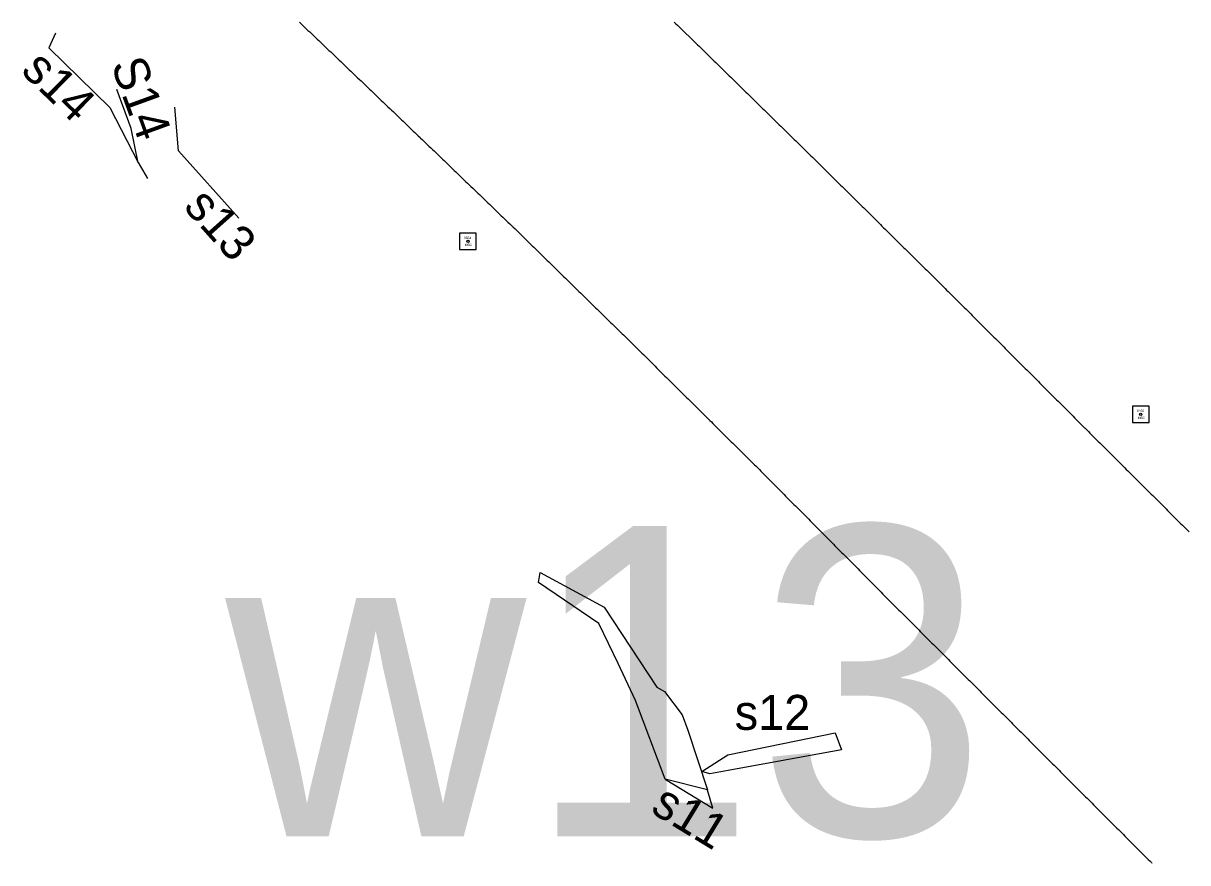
# Model space of a CAD drawing. Extents: x 205929 to 2357175, y -1785700 to 846739.
# Drawn here: x 2019173.3 to 2019672.3, y 816619 to 816978.9 of the extents above; entities that cross this region are included whole.
import ezdxf

# ---------------------------------------------------------------- set-up
doc = ezdxf.new("R2010")
doc.units = 0
for name, color, linetype in [('Default', 7, 'Continuous'), ('RD_EV_JTrib', 7, 'Continuous'), ('RD_EV_JW', 7, 'Continuous'), ('RD_EV_TX', 7, 'Continuous'), ('RD_HC_Survey', 7, 'Continuous'), ('RD_HC_txCode', 7, 'Continuous'), ('RD_Sketch1', 7, 'Continuous'), ('RD_SMD_Locator', 7, 'Continuous')]:
    doc.layers.add(name, color=color, linetype=linetype)

# ---------------------------------------------------------------- blocks, each defined once
blk = doc.blocks.new('POL00034')
at = {"layer": 'Default'}
blk.add_lwpolyline([(2.23, 0.45), (4.16, -2.1), (4.78, -3.77), (6.93, -10.27), (2.31, -9.09), (-0.91, -0.52), (-2.8, 3.49), (-4.89, 7.87), (-11.45, 12.32), (-11.27, 13.43), (-4.32, 9.65), (1.43, 0.94)], close=True, dxfattribs=at)
blk = doc.blocks.new('POL00048')
at = {"layer": 'Default'}
blk.add_lwpolyline([(-5.27, -0.11), (6.41, 2.28), (7.1, 0.43), (-5.25, -1.82), (-7.25, -2.18), (-8.1, -1.93)], close=True, dxfattribs=at)
blk = doc.blocks.new('ARC0002H')
at = {"layer": 'Default'}
blk.add_lwpolyline([(-3.48, 2.12), (1.72, -1.04), (1.14, 0.94)], dxfattribs=at)
blk = doc.blocks.new('ARC0002I')
at = {"layer": 'Default'}
blk.add_lwpolyline([(-5.07, 7.29), (-5.83, 5.69), (0.84, -0.82), (3.92, -6.81), (4.91, -8.56)], dxfattribs=at)
blk = doc.blocks.new('ARC0002J')
at = {"layer": 'Default'}
blk.add_lwpolyline([(4.87, -5.45), (-1.7, 1.9), (-2.09, 6.64)], dxfattribs=at)
blk = doc.blocks.new('ARC00038')
at = {"layer": 'Default'}
blk.add_lwpolyline([(0.9, -4.08), (0.13, -0.35), (-1.41, 3.89), (-1.41, 3.85)], dxfattribs=at)

msp = doc.modelspace()

# ---------------------------------------------------------------- linework, layer by layer
at = {"layer": 'RD_HC_Survey'}
for points in [[(2019367.37, 816888.95), (2019360.3, 816888.95), (2019360.3, 816881.88), (2019367.37, 816881.88)], [(2019655.76, 816814.79), (2019648.69, 816814.79), (2019648.69, 816807.72), (2019655.76, 816807.72)]]:
    msp.add_lwpolyline(points, close=True, dxfattribs=at)
for centre in [(2019363.84, 816885.42), (2019652.22, 816811.25)]:
    msp.add_circle(centre, 0.5, dxfattribs=at)
at = {"layer": 'RD_Sketch1'}
for points in [[(2019291.71, 816979.34), (2019292.44, 816978.65), (2019293.16, 816977.96), (2019293.89, 816977.28), (2019294.62, 816976.59), (2019295.34, 816975.9), (2019296.07, 816975.21), (2019296.07, 816975.21), (2019296.8, 816974.53), (2019297.52, 816973.84), (2019298.25, 816973.15), (2019298.98, 816972.47), (2019299.29, 816972.17), (2019300.01, 816971.48), (2019300.73, 816970.79), (2019301.45, 816970.09), (2019302.18, 816969.4), (2019302.9, 816968.71), (2019303.62, 816968.02), (2019304.34, 816967.33), (2019305.07, 816966.64), (2019305.79, 816965.94), (2019306.51, 816965.25), (2019307.23, 816964.56), (2019307.95, 816963.87), (2019308.68, 816963.18), (2019309.4, 816962.49), (2019310.12, 816961.79), (2019310.84, 816961.1), (2019311.57, 816960.41), (2019312.29, 816959.72), (2019313.01, 816959.03), (2019313.73, 816958.34), (2019314.45, 816957.64), (2019315.18, 816956.95), (2019315.9, 816956.26), (2019316.62, 816955.57), (2019317.34, 816954.88), (2019318.06, 816954.19), (2019318.79, 816953.49), (2019319.51, 816952.8), (2019320.23, 816952.11), (2019320.95, 816951.42), (2019321.68, 816950.73), (2019322.4, 816950.04), (2019323.12, 816949.34), (2019323.84, 816948.65), (2019324.56, 816947.96), (2019325.29, 816947.27), (2019326.01, 816946.58), (2019326.73, 816945.89), (2019327.45, 816945.19), (2019328.17, 816944.5), (2019328.9, 816943.81), (2019329.62, 816943.12), (2019330.34, 816942.43), (2019331.06, 816941.74), (2019331.79, 816941.04), (2019332.51, 816940.35), (2019333.23, 816939.66), (2019333.95, 816938.97), (2019334.67, 816938.28), (2019335.4, 816937.59), (2019336.12, 816936.89), (2019336.84, 816936.2), (2019337.56, 816935.51), (2019338.29, 816934.82), (2019339.01, 816934.13), (2019339.73, 816933.44), (2019340.45, 816932.74), (2019341.17, 816932.05), (2019341.9, 816931.36), (2019341.9, 816931.36), (2019342.62, 816930.67), (2019343.34, 816929.98), (2019343.59, 816929.74), (2019344.31, 816929.05), (2019345.03, 816928.35), (2019345.75, 816927.66), (2019346.47, 816926.96), (2019347.19, 816926.27), (2019347.91, 816925.58), (2019348.63, 816924.88), (2019349.35, 816924.19), (2019350.07, 816923.5), (2019350.79, 816922.8), (2019351.51, 816922.11), (2019352.23, 816921.41), (2019352.95, 816920.72), (2019353.67, 816920.03), (2019354.39, 816919.33), (2019355.11, 816918.64), (2019355.83, 816917.95), (2019356.55, 816917.25), (2019357.27, 816916.56), (2019357.99, 816915.86), (2019358.71, 816915.17), (2019359.43, 816914.48), (2019360.15, 816913.78), (2019360.87, 816913.09), (2019361.59, 816912.4), (2019362.31, 816911.7), (2019363.03, 816911.01), (2019363.75, 816910.31), (2019364.47, 816909.62), (2019365.19, 816908.93), (2019365.91, 816908.23), (2019366.63, 816907.54), (2019367.35, 816906.85), (2019368.07, 816906.15), (2019368.79, 816905.46), (2019369.52, 816904.76), (2019370.24, 816904.07), (2019370.96, 816903.38), (2019371.68, 816902.68), (2019372.4, 816901.99), (2019373.12, 816901.3), (2019373.84, 816900.6), (2019374.56, 816899.91), (2019375.28, 816899.21), (2019376, 816898.52), (2019376.72, 816897.83), (2019377.44, 816897.13), (2019378.16, 816896.44), (2019378.88, 816895.75), (2019379.6, 816895.05), (2019380.32, 816894.36), (2019381.04, 816893.66), (2019381.76, 816892.97), (2019382.48, 816892.28), (2019383.2, 816891.58), (2019383.92, 816890.89), (2019384.64, 816890.2), (2019385.36, 816889.5), (2019386.08, 816888.81), (2019386.43, 816888.47), (2019387.15, 816887.77), (2019387.15, 816887.77), (2019387.86, 816887.07), (2019388.58, 816886.37), (2019389.29, 816885.67), (2019390.01, 816884.97), (2019390.72, 816884.27), (2019391.44, 816883.57), (2019392.15, 816882.87), (2019392.86, 816882.17), (2019393.58, 816881.47), (2019394.29, 816880.77), (2019395.01, 816880.07), (2019395.72, 816879.37), (2019396.44, 816878.68), (2019397.15, 816877.98), (2019397.87, 816877.28), (2019398.58, 816876.58), (2019399.3, 816875.88), (2019400.01, 816875.18), (2019400.73, 816874.48), (2019401.44, 816873.78), (2019402.16, 816873.08), (2019402.87, 816872.38), (2019403.58, 816871.68), (2019404.3, 816870.98), (2019405.01, 816870.28), (2019405.73, 816869.58), (2019406.44, 816868.88), (2019407.16, 816868.18), (2019407.87, 816867.48), (2019408.59, 816866.78), (2019409.3, 816866.08), (2019410.02, 816865.39), (2019410.73, 816864.69), (2019411.45, 816863.99), (2019412.16, 816863.29), (2019412.87, 816862.59), (2019413.59, 816861.89), (2019414.3, 816861.19), (2019415.02, 816860.49), (2019415.73, 816859.79), (2019416.45, 816859.09), (2019417.16, 816858.39), (2019417.88, 816857.69), (2019418.59, 816856.99), (2019419.31, 816856.29), (2019420.02, 816855.59), (2019420.74, 816854.89), (2019421.45, 816854.19), (2019422.17, 816853.49), (2019422.88, 816852.79), (2019423.59, 816852.1), (2019424.31, 816851.4), (2019425.02, 816850.7), (2019425.74, 816850), (2019426.45, 816849.3), (2019427.17, 816848.6), (2019427.88, 816847.9), (2019428.6, 816847.2), (2019429.31, 816846.5), (2019430.03, 816845.8), (2019430.55, 816845.29), (2019431.26, 816844.59), (2019431.97, 816843.88), (2019432.68, 816843.18), (2019432.68, 816843.18), (2019433.39, 816842.47), (2019434.1, 816841.77), (2019434.81, 816841.07), (2019435.52, 816840.36), (2019436.23, 816839.66), (2019436.94, 816838.95), (2019437.65, 816838.25), (2019438.36, 816837.55), (2019439.07, 816836.84), (2019439.78, 816836.14), (2019440.49, 816835.43), (2019441.2, 816834.73), (2019441.91, 816834.03), (2019442.62, 816833.32), (2019443.33, 816832.62), (2019444.04, 816831.91), (2019444.75, 816831.21), (2019445.46, 816830.51), (2019446.17, 816829.8), (2019446.88, 816829.1), (2019447.59, 816828.39), (2019448.3, 816827.69), (2019449.01, 816826.98), (2019449.72, 816826.28), (2019450.43, 816825.58), (2019451.14, 816824.87), (2019451.85, 816824.17), (2019452.56, 816823.46), (2019453.27, 816822.76), (2019453.98, 816822.06), (2019454.69, 816821.35), (2019455.4, 816820.65), (2019456.11, 816819.94), (2019456.82, 816819.24), (2019457.53, 816818.54), (2019458.24, 816817.83), (2019458.95, 816817.13), (2019459.66, 816816.42), (2019460.37, 816815.72), (2019461.08, 816815.02), (2019461.79, 816814.31), (2019462.5, 816813.61), (2019463.21, 816812.9), (2019463.92, 816812.2), (2019464.63, 816811.5), (2019465.34, 816810.79), (2019466.05, 816810.09), (2019466.76, 816809.38), (2019467.47, 816808.68), (2019468.18, 816807.97), (2019468.89, 816807.27), (2019469.6, 816806.57), (2019470.31, 816805.86), (2019471.02, 816805.16), (2019471.73, 816804.45), (2019472.44, 816803.75), (2019473.15, 816803.05), (2019473.86, 816802.34), (2019474.57, 816801.64), (2019475.28, 816800.93), (2019475.99, 816800.23), (2019476.7, 816799.53), (2019477.41, 816798.82), (2019478.12, 816798.12), (2019478.12, 816798.12), (2019478.83, 816797.41), (2019479.54, 816796.71), (2019480.25, 816796.01), (2019480.96, 816795.3), (2019481.67, 816794.6), (2019482.38, 816793.89), (2019483.09, 816793.19), (2019483.8, 816792.48), (2019484.51, 816791.78), (2019485.22, 816791.08), (2019485.93, 816790.37), (2019486.64, 816789.67), (2019487.35, 816788.96), (2019488.05, 816788.27), (2019488.76, 816787.56), (2019489.46, 816786.85), (2019490.17, 816786.14), (2019490.87, 816785.43), (2019491.58, 816784.72), (2019492.28, 816784.01), (2019492.98, 816783.3), (2019493.69, 816782.6), (2019494.39, 816781.89), (2019495.1, 816781.18), (2019495.8, 816780.47), (2019496.51, 816779.76), (2019497.21, 816779.05), (2019497.92, 816778.34), (2019498.62, 816777.63), (2019499.32, 816776.92), (2019500.03, 816776.21), (2019500.73, 816775.5), (2019501.44, 816774.79), (2019502.14, 816774.08), (2019502.85, 816773.37), (2019503.55, 816772.66), (2019504.26, 816771.95), (2019504.96, 816771.24), (2019505.66, 816770.53), (2019506.37, 816769.82), (2019507.07, 816769.11), (2019507.78, 816768.4), (2019508.48, 816767.69), (2019509.19, 816766.98), (2019509.89, 816766.27), (2019510.6, 816765.56), (2019511.3, 816764.85), (2019512.01, 816764.14), (2019512.71, 816763.43), (2019513.41, 816762.72), (2019514.12, 816762.01), (2019514.82, 816761.3), (2019515.53, 816760.59), (2019516.23, 816759.88), (2019516.94, 816759.18), (2019517.64, 816758.47), (2019518.35, 816757.76), (2019519.05, 816757.05), (2019519.75, 816756.34), (2019520.46, 816755.63), (2019521.16, 816754.92), (2019521.87, 816754.21), (2019522.57, 816753.5), (2019523.28, 816752.79), (2019523.28, 816752.79), (2019523.98, 816752.08), (2019524.69, 816751.37), (2019525.39, 816750.66), (2019526.09, 816749.95), (2019526.8, 816749.24), (2019527.5, 816748.53), (2019528.21, 816747.82), (2019528.91, 816747.11), (2019529.62, 816746.4), (2019530.32, 816745.69), (2019531.03, 816744.98), (2019531.73, 816744.27), (2019532.44, 816743.56), (2019533.14, 816742.85), (2019533.84, 816742.14), (2019534.55, 816741.43), (2019535.25, 816740.72), (2019535.96, 816740.01), (2019536.66, 816739.3), (2019537.37, 816738.59), (2019538.07, 816737.88), (2019538.78, 816737.17), (2019539.48, 816736.47), (2019540.18, 816735.76), (2019540.89, 816735.05), (2019541.59, 816734.34), (2019542.3, 816733.63), (2019543, 816732.92), (2019543.71, 816732.21), (2019544.31, 816731.6), (2019545.02, 816730.89), (2019545.72, 816730.18), (2019546.43, 816729.47), (2019547.14, 816728.77), (2019547.84, 816728.06), (2019548.55, 816727.35), (2019549.26, 816726.64), (2019549.96, 816725.94), (2019550.67, 816725.23), (2019551.38, 816724.52), (2019552.08, 816723.81), (2019552.79, 816723.1), (2019553.5, 816722.4), (2019554.2, 816721.69), (2019554.91, 816720.98), (2019555.61, 816720.27), (2019556.32, 816719.57), (2019557.03, 816718.86), (2019557.73, 816718.15), (2019558.44, 816717.44), (2019559.15, 816716.73), (2019559.85, 816716.03), (2019560.56, 816715.32), (2019561.27, 816714.61), (2019561.97, 816713.9), (2019562.68, 816713.2), (2019563.39, 816712.49), (2019564.09, 816711.78), (2019564.8, 816711.07), (2019565.5, 816710.36), (2019566.21, 816709.66), (2019566.92, 816708.95), (2019567.62, 816708.24), (2019568.33, 816707.53), (2019568.33, 816707.53), (2019569.04, 816706.83), (2019569.74, 816706.12), (2019570.45, 816705.41), (2019571.16, 816704.7), (2019571.86, 816703.99), (2019572.57, 816703.29), (2019573.28, 816702.58), (2019573.98, 816701.87), (2019574.69, 816701.16), (2019575.39, 816700.46), (2019576.1, 816699.75), (2019576.81, 816699.04), (2019577.51, 816698.33), (2019578.22, 816697.62), (2019578.93, 816696.92), (2019579.63, 816696.21), (2019580.34, 816695.5), (2019581.05, 816694.79), (2019581.75, 816694.09), (2019582.46, 816693.38), (2019583.17, 816692.67), (2019583.87, 816691.96), (2019584.58, 816691.26), (2019585.28, 816690.55), (2019585.99, 816689.84), (2019586.7, 816689.13), (2019587.4, 816688.42), (2019588.11, 816687.72), (2019588.82, 816687.01), (2019589.52, 816686.3), (2019590.23, 816685.59), (2019590.94, 816684.89), (2019591.64, 816684.18), (2019592.35, 816683.47), (2019593.06, 816682.76), (2019593.76, 816682.05), (2019594.47, 816681.35), (2019595.17, 816680.64), (2019595.88, 816679.93), (2019596.59, 816679.22), (2019597.29, 816678.52), (2019598, 816677.81), (2019598.71, 816677.1), (2019599.41, 816676.39), (2019600.12, 816675.68), (2019600.2, 816675.6), (2019600.91, 816674.9), (2019601.61, 816674.19), (2019602.32, 816673.48), (2019603.03, 816672.77), (2019603.74, 816672.07), (2019604.44, 816671.36), (2019605.15, 816670.65), (2019605.86, 816669.94), (2019606.56, 816669.24), (2019607.27, 816668.53), (2019607.98, 816667.82), (2019608.68, 816667.12), (2019609.39, 816666.41), (2019610.1, 816665.7), (2019610.8, 816664.99), (2019611.51, 816664.29), (2019612.22, 816663.58), (2019612.93, 816662.87), (2019612.93, 816662.87), (2019613.63, 816662.16), (2019614.34, 816661.46), (2019615.05, 816660.75), (2019615.75, 816660.04), (2019616.46, 816659.34), (2019617.17, 816658.63), (2019617.87, 816657.92), (2019618.58, 816657.21), (2019619.29, 816656.51), (2019619.99, 816655.8), (2019620.7, 816655.09), (2019621.41, 816654.38), (2019622.11, 816653.68), (2019622.82, 816652.97), (2019623.53, 816652.26), (2019624.24, 816651.56), (2019624.94, 816650.85), (2019625.65, 816650.14), (2019626.36, 816649.43), (2019627.06, 816648.73), (2019627.77, 816648.02), (2019628.48, 816647.31), (2019629.18, 816646.6), (2019629.89, 816645.9), (2019630.6, 816645.19), (2019631.3, 816644.48), (2019632.01, 816643.78), (2019632.72, 816643.07), (2019633.43, 816642.36), (2019634.13, 816641.65), (2019634.84, 816640.95), (2019635.55, 816640.24), (2019636.25, 816639.53), (2019636.96, 816638.82), (2019637.67, 816638.12), (2019638.37, 816637.41), (2019639.08, 816636.7), (2019639.79, 816635.99), (2019640.49, 816635.29), (2019641.2, 816634.58), (2019641.91, 816633.87), (2019642.61, 816633.17), (2019643.32, 816632.46), (2019644.03, 816631.75), (2019644.74, 816631.04), (2019645.44, 816630.34), (2019646.15, 816629.63), (2019646.86, 816628.92), (2019647.56, 816628.21), (2019648.27, 816627.51), (2019648.98, 816626.8), (2019649.68, 816626.09), (2019650.39, 816625.39), (2019651.1, 816624.68), (2019651.8, 816623.97), (2019652.51, 816623.26), (2019653.22, 816622.56), (2019653.93, 816621.85), (2019654.63, 816621.14), (2019655.34, 816620.43), (2019656.05, 816619.73), (2019656.75, 816619.02), (2019656.93, 816618.84)], [(2019452.23, 816979.45), (2019452.95, 816978.75), (2019453.67, 816978.06), (2019454.39, 816977.36), (2019455.11, 816976.67), (2019455.83, 816975.97), (2019456.55, 816975.28), (2019457.27, 816974.58), (2019458.64, 816973.25), (2019459.36, 816972.55), (2019460.07, 816971.85), (2019460.79, 816971.15), (2019461.5, 816970.45), (2019462.22, 816969.75), (2019462.93, 816969.05), (2019463.64, 816968.35), (2019464.36, 816967.65), (2019464.36, 816967.65), (2019465.07, 816966.95), (2019465.79, 816966.25), (2019466.5, 816965.55), (2019467.22, 816964.85), (2019467.93, 816964.15), (2019468.64, 816963.45), (2019469.36, 816962.75), (2019470.07, 816962.05), (2019470.79, 816961.35), (2019471.5, 816960.65), (2019472.22, 816959.95), (2019472.93, 816959.25), (2019473.64, 816958.55), (2019474.36, 816957.85), (2019475.07, 816957.16), (2019475.79, 816956.46), (2019476.5, 816955.76), (2019477.22, 816955.06), (2019477.93, 816954.36), (2019478.64, 816953.66), (2019479.36, 816952.96), (2019480.07, 816952.26), (2019480.79, 816951.56), (2019481.5, 816950.86), (2019482.22, 816950.16), (2019482.93, 816949.46), (2019483.64, 816948.76), (2019484.36, 816948.06), (2019485.07, 816947.36), (2019485.79, 816946.66), (2019486.5, 816945.96), (2019487.22, 816945.26), (2019487.93, 816944.56), (2019488.64, 816943.86), (2019489.36, 816943.16), (2019490.07, 816942.46), (2019490.79, 816941.76), (2019491.5, 816941.06), (2019492.22, 816940.36), (2019492.93, 816939.66), (2019493.64, 816938.96), (2019494.36, 816938.26), (2019495.07, 816937.56), (2019495.79, 816936.86), (2019496.5, 816936.16), (2019497.22, 816935.46), (2019497.93, 816934.76), (2019498.64, 816934.06), (2019499.36, 816933.36), (2019500.07, 816932.66), (2019500.79, 816931.96), (2019501.5, 816931.26), (2019502.22, 816930.56), (2019502.93, 816929.86), (2019503.64, 816929.16), (2019504.36, 816928.46), (2019505.07, 816927.76), (2019505.79, 816927.06), (2019506.5, 816926.36), (2019507.22, 816925.66), (2019507.93, 816924.96), (2019508.64, 816924.26), (2019509.36, 816923.56), (2019510.07, 816922.86), (2019510.07, 816922.86), (2019510.79, 816922.16), (2019511.5, 816921.46), (2019512.22, 816920.76), (2019512.93, 816920.06), (2019513.64, 816919.36), (2019514.36, 816918.66), (2019515.01, 816918.03), (2019515.72, 816917.32), (2019516.43, 816916.62), (2019517.14, 816915.91), (2019517.85, 816915.21), (2019518.56, 816914.51), (2019519.28, 816913.8), (2019519.99, 816913.1), (2019520.7, 816912.4), (2019521.41, 816911.69), (2019522.12, 816910.99), (2019522.83, 816910.29), (2019523.54, 816909.58), (2019524.25, 816908.88), (2019524.96, 816908.18), (2019525.67, 816907.47), (2019526.38, 816906.77), (2019527.09, 816906.07), (2019527.8, 816905.36), (2019528.51, 816904.66), (2019529.23, 816903.96), (2019529.94, 816903.25), (2019530.65, 816902.55), (2019531.36, 816901.85), (2019532.07, 816901.14), (2019532.78, 816900.44), (2019533.49, 816899.73), (2019534.2, 816899.03), (2019534.91, 816898.33), (2019535.62, 816897.62), (2019536.33, 816896.92), (2019537.04, 816896.22), (2019537.75, 816895.51), (2019538.46, 816894.81), (2019539.17, 816894.11), (2019539.89, 816893.4), (2019540.6, 816892.7), (2019541.31, 816892), (2019542.02, 816891.29), (2019542.73, 816890.59), (2019543.44, 816889.89), (2019544.15, 816889.18), (2019544.86, 816888.48), (2019545.57, 816887.78), (2019546.28, 816887.07), (2019546.99, 816886.37), (2019547.7, 816885.67), (2019548.41, 816884.96), (2019549.12, 816884.26), (2019549.84, 816883.55), (2019550.55, 816882.85), (2019551.26, 816882.15), (2019551.97, 816881.44), (2019552.68, 816880.74), (2019553.39, 816880.04), (2019554.1, 816879.33), (2019554.81, 816878.63), (2019555.52, 816877.93), (2019555.52, 816877.93), (2019556.23, 816877.22), (2019556.94, 816876.52), (2019557.65, 816875.82), (2019558.36, 816875.11), (2019559.07, 816874.41), (2019559.78, 816873.71), (2019560.5, 816873), (2019561.21, 816872.3), (2019561.92, 816871.6), (2019562.63, 816870.89), (2019563.34, 816870.19), (2019564.05, 816869.49), (2019564.76, 816868.78), (2019565.47, 816868.08), (2019566.18, 816867.37), (2019566.89, 816866.67), (2019567.6, 816865.97), (2019568.31, 816865.26), (2019569.02, 816864.56), (2019569.73, 816863.86), (2019570.45, 816863.15), (2019571.16, 816862.45), (2019571.53, 816862.08), (2019572.24, 816861.37), (2019572.95, 816860.66), (2019573.65, 816859.96), (2019574.36, 816859.25), (2019575.07, 816858.54), (2019575.77, 816857.84), (2019576.48, 816857.13), (2019577.19, 816856.42), (2019577.9, 816855.72), (2019578.6, 816855.01), (2019579.31, 816854.3), (2019580.02, 816853.6), (2019580.73, 816852.89), (2019581.43, 816852.18), (2019582.14, 816851.47), (2019582.85, 816850.77), (2019583.55, 816850.06), (2019584.26, 816849.35), (2019584.97, 816848.65), (2019585.68, 816847.94), (2019586.38, 816847.23), (2019587.09, 816846.53), (2019587.8, 816845.82), (2019588.5, 816845.11), (2019589.21, 816844.41), (2019589.92, 816843.7), (2019590.63, 816842.99), (2019591.33, 816842.28), (2019592.04, 816841.58), (2019592.75, 816840.87), (2019593.45, 816840.16), (2019594.16, 816839.46), (2019594.87, 816838.75), (2019595.58, 816838.04), (2019596.28, 816837.34), (2019596.99, 816836.63), (2019597.7, 816835.92), (2019598.41, 816835.21), (2019599.11, 816834.51), (2019599.82, 816833.8), (2019600.53, 816833.09), (2019600.53, 816833.09), (2019601.23, 816832.39), (2019601.94, 816831.68), (2019602.65, 816830.97), (2019603.36, 816830.27), (2019604.06, 816829.56), (2019604.77, 816828.85), (2019605.48, 816828.15), (2019606.18, 816827.44), (2019606.89, 816826.73), (2019607.6, 816826.02), (2019608.31, 816825.32), (2019609.01, 816824.61), (2019609.72, 816823.9), (2019610.43, 816823.2), (2019611.13, 816822.49), (2019611.84, 816821.78), (2019612.55, 816821.08), (2019613.26, 816820.37), (2019613.96, 816819.66), (2019614.67, 816818.96), (2019615.38, 816818.25), (2019616.09, 816817.54), (2019616.79, 816816.83), (2019617.5, 816816.13), (2019618.21, 816815.42), (2019618.91, 816814.71), (2019619.62, 816814.01), (2019620.33, 816813.3), (2019621.04, 816812.59), (2019621.74, 816811.89), (2019622.45, 816811.18), (2019623.16, 816810.47), (2019623.86, 816809.77), (2019624.57, 816809.06), (2019625.28, 816808.35), (2019625.99, 816807.64), (2019626.69, 816806.94), (2019627.4, 816806.23), (2019628.11, 816805.52), (2019628.31, 816805.32), (2019629.02, 816804.62), (2019629.73, 816803.91), (2019630.43, 816803.2), (2019631.14, 816802.5), (2019631.85, 816801.79), (2019632.56, 816801.09), (2019633.27, 816800.38), (2019633.97, 816799.67), (2019634.68, 816798.97), (2019635.39, 816798.26), (2019636.1, 816797.56), (2019636.81, 816796.85), (2019637.52, 816796.14), (2019638.22, 816795.44), (2019638.93, 816794.73), (2019639.64, 816794.03), (2019640.35, 816793.32), (2019641.06, 816792.61), (2019641.76, 816791.91), (2019642.47, 816791.2), (2019643.18, 816790.5), (2019643.89, 816789.79), (2019644.6, 816789.08), (2019645.31, 816788.38), (2019645.31, 816788.38), (2019646.01, 816787.67), (2019646.72, 816786.97), (2019647.43, 816786.26), (2019648.14, 816785.55), (2019648.85, 816784.85), (2019649.55, 816784.14), (2019650.26, 816783.44), (2019650.97, 816782.73), (2019651.68, 816782.02), (2019652.39, 816781.32), (2019653.1, 816780.61), (2019653.8, 816779.91), (2019654.51, 816779.2), (2019655.22, 816778.49), (2019655.93, 816777.79), (2019656.64, 816777.08), (2019657.34, 816776.38), (2019658.05, 816775.67), (2019658.76, 816774.96), (2019659.47, 816774.26), (2019660.18, 816773.55), (2019660.88, 816772.85), (2019661.59, 816772.14), (2019662.3, 816771.43), (2019663.01, 816770.73), (2019663.72, 816770.02), (2019664.43, 816769.32), (2019665.13, 816768.61), (2019665.84, 816767.9), (2019666.55, 816767.2), (2019667.26, 816766.49), (2019667.97, 816765.79), (2019668.67, 816765.08), (2019669.38, 816764.37), (2019670.09, 816763.67), (2019670.8, 816762.96), (2019671.51, 816762.26), (2019672.22, 816761.55), (2019672.92, 816760.84)]]:
    msp.add_lwpolyline(points, dxfattribs=at)
at = {"layer": 'RD_SMD_Locator'}
for centre in [(2019363.84, 816885.42), (2019652.22, 816811.25)]:
    msp.add_circle(centre, 0.001, dxfattribs=at)

# ---------------------------------------------------------------- block references
at = {"layer": 'RD_EV_JTrib', "xscale": 3.937007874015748, "yscale": 3.937007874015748}
for name, p in [('ARC0002I', (2019207.17, 816946.03)), ('ARC00038', (2019219, 816935.2)), ('ARC0002J', (2019246.55, 816916.81)), ('POL00048', (2019496.04, 816665.68)), ('ARC0002H', (2019462.05, 816646.47))]:
    msp.add_blockref(name, p, dxfattribs=at)
at = {"layer": 'RD_EV_JW', "xscale": 3.937007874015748, "yscale": 3.937007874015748}
msp.add_blockref('POL00034', (2019439.26, 816690.61), dxfattribs=at)

# ---------------------------------------------------------------- texts
at = {"layer": 'RD_EV_TX'}
for s, rotation, p in [('s14', 315.6783, (2019171.87, 816958.13)), ('S14', 289.9831, (2019210.78, 816961.22)), ('s13', 311.7468, (2019241.62, 816899.96)), ('s11', 328.6572, (2019441.6, 816640.9))]:
    msp.add_text(s, height=15, rotation=rotation, dxfattribs=at).set_placement(p)
for s, height, p in [('w13', 133.064, (2019260.07, 816630.29)), ('s12', 15, (2019478.2, 816675.95))]:
    msp.add_text(s, height=height, dxfattribs=at).set_placement(p)
at = {"layer": 'RD_HC_txCode'}
for s, p in [('8564', (2019362.19, 816886.42)), ('MSC', (2019362.52, 816883.42)), ('8466', (2019650.55, 816812.25)), ('MSC', (2019650.91, 816809.25))]:
    msp.add_text(s, height=1, dxfattribs=at).set_placement(p)

doc.saveas('drawing.dxf')
